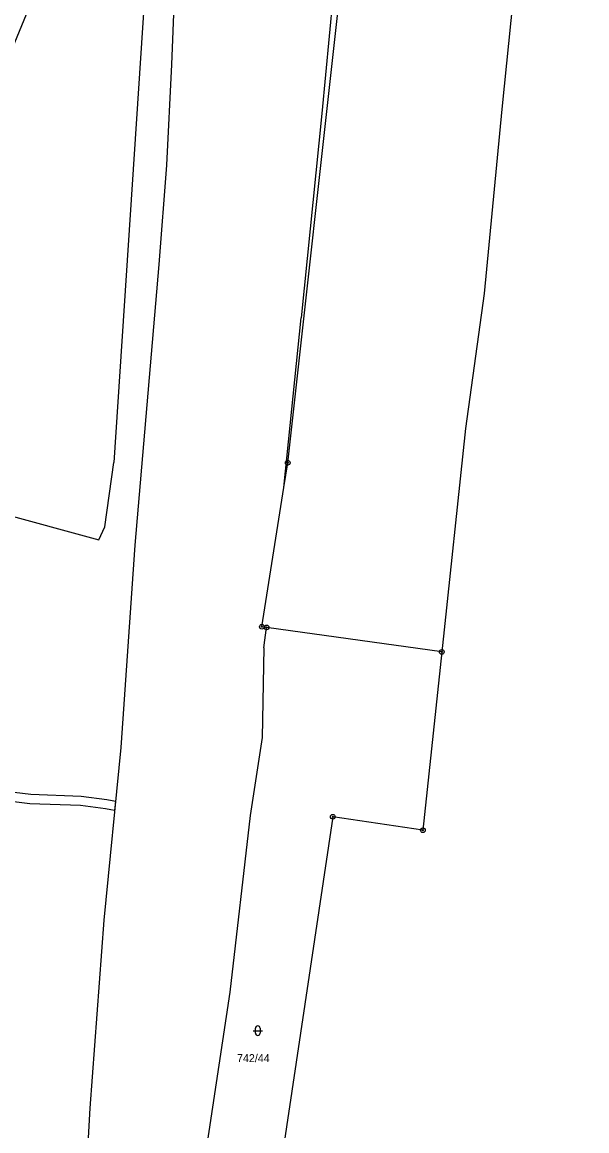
# Model space of a CAD drawing. Extents: x -755819 to -753140, y -1169796 to -1166000.
# Drawn here: x -754609.3 to -754489.2, y -1168020.1 to -1167784.6 of the extents above; entities that cross this region are included whole.
import ezdxf

# ---------------------------------------------------------------- set-up
doc = ezdxf.new("R2010")
doc.units = 0
for name, color, linetype in [('Vrstva 1', 7, 'Continuous'), ('Vrstva 13', 7, 'Continuous'), ('Vrstva 18', 7, 'Continuous'), ('Vrstva 24', 7, 'Continuous'), ('Vrstva 25', 7, 'Continuous'), ('Vrstva 27', 7, 'Continuous')]:
    doc.layers.add(name, color=color, linetype=linetype)

msp = doc.modelspace()

# ---------------------------------------------------------------- linework, layer by layer
at = {"layer": 'Vrstva 1'}
for p, q in [((-754552.83, -1167878.22), (-754534.04, -1167709.39)), ((-754580.02, -1167730.17), (-754589.79, -1167878.17)), ((-754576.1, -1167756.85), (-754577.55, -1167793.63)), ((-754542.46, -1167771.3), (-754545.61, -1167804.01)), ((-754577.55, -1167793.63), (-754578.6, -1167815.03)), ((-754545.61, -1167804.01), (-754549.96, -1167847.46)), ((-754578.6, -1167815.03), (-754580.27, -1167836.08)), ((-754580.27, -1167836.08), (-754585.32, -1167895.69)), ((-754553.67, -1167883.5), (-754549.96, -1167847.46)), ((-754591.71, -1167891.8), (-754589.79, -1167878.17)), ((-754553.67, -1167883.5), (-754552.83, -1167878.22)), ((-754558.33, -1167913.05), (-754553.67, -1167883.5)), ((-754617.01, -1167888.04), (-754592.97, -1167894.58)), ((-754592.97, -1167894.58), (-754591.71, -1167891.8)), ((-754585.32, -1167895.69), (-754588.32, -1167938.67)), ((-754557.33, -1167913.19), (-754558.33, -1167913.05)), ((-754557.91, -1167917.52), (-754557.33, -1167913.19)), ((-754520.07, -1167918.39), (-754557.33, -1167913.19)), ((-754557.91, -1167917.52), (-754558.27, -1167936.59)), ((-754588.32, -1167938.67), (-754591.94, -1167975.39)), ((-754558.27, -1167936.59), (-754560.8, -1167953.17)), ((-754560.8, -1167953.17), (-754565.11, -1167990.68)), ((-754591.94, -1167975.39), (-754594.95, -1168015.34)), ((-754565.11, -1167990.68), (-754570.42, -1168025.66)), ((-754594.95, -1168015.34), (-754595.86, -1168032.74))]:
    msp.add_line(p, q, dxfattribs=at)
at = {"layer": 'Vrstva 13'}
for p, q in [((-754489.22, -1167624.37), (-754507.29, -1167803.09)), ((-754507.29, -1167803.09), (-754511.04, -1167842.28)), ((-754511.04, -1167842.28), (-754515.02, -1167870.94)), ((-754515.02, -1167870.94), (-754520.07, -1167918.39)), ((-754520.07, -1167918.39), (-754524.1, -1167956.28)), ((-754543.25, -1167953.4), (-754564.88, -1168098.39)), ((-754524.1, -1167956.28), (-754543.25, -1167953.4))]:
    msp.add_line(p, q, dxfattribs=at)
at = {"layer": 'Vrstva 24'}
for centre, radius in [((-754552.83, -1167878.22), 0.5), ((-754552.83, -1167878.22), 0.1), ((-754558.33, -1167913.05), 0.5), ((-754557.33, -1167913.19), 0.5), ((-754558.33, -1167913.05), 0.1), ((-754557.33, -1167913.19), 0.1), ((-754520.07, -1167918.39), 0.5), ((-754520.07, -1167918.39), 0.1), ((-754543.25, -1167953.4), 0.5), ((-754543.25, -1167953.4), 0.1), ((-754524.1, -1167956.28), 0.5), ((-754524.1, -1167956.28), 0.1)]:
    msp.add_circle(centre, radius, dxfattribs=at)
at = {"layer": 'Vrstva 25'}
for p, q in [((-754560.2, -1167998.85), (-754558.2, -1167998.85)), ((-754559.7, -1167999.35), (-754559.7, -1167998.35)), ((-754558.7, -1167998.35), (-754558.7, -1167999.35))]:
    msp.add_line(p, q, dxfattribs=at)
for centre, start, end in [((-754559.2, -1167998.35), 0, 180), ((-754559.2, -1167999.35), 180, 0)]:
    msp.add_arc(centre, 0.5, start, end, dxfattribs=at)
at = {"layer": 'Vrstva 27'}
for p, q in [((-754586.5, -1167729.83), (-754621.98, -1167815.7)), ((-754622.44, -1167946.84), (-754607.5, -1167948.64)), ((-754607.66, -1167950.64), (-754622.62, -1167948.84)), ((-754607.5, -1167948.64), (-754596.75, -1167949.03)), ((-754596.75, -1167949.03), (-754591.29, -1167949.76)), ((-754591.29, -1167949.76), (-754590.14, -1167949.98)), ((-754590.14, -1167949.98), (-754589.45, -1167950.09)), ((-754589.45, -1167950.09), (-754589.64, -1167952.09)), ((-754596.91, -1167951.03), (-754607.66, -1167950.64)), ((-754591.61, -1167951.74), (-754596.91, -1167951.03)), ((-754590.48, -1167951.96), (-754591.61, -1167951.74)), ((-754589.64, -1167952.09), (-754590.48, -1167951.96))]:
    msp.add_line(p, q, dxfattribs=at)

# ---------------------------------------------------------------- texts
at = {"layer": 'Vrstva 18'}
msp.add_text('742/44', height=1.7, dxfattribs=at).set_placement((-754563.62, -1168005.54))

doc.saveas('drawing.dxf')
